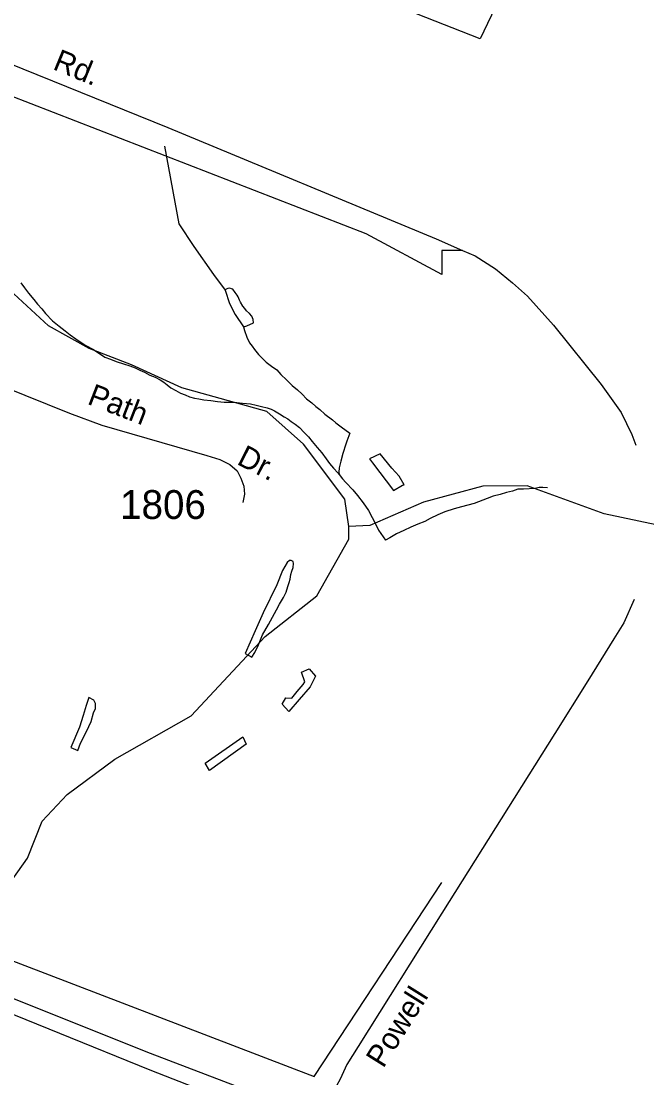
# Model space of a CAD drawing. Extents: x 2260773 to 2342389, y 552869 to 618546.
# Drawn here: x 2327254 to 2329965, y 580441 to 585022 of the extents above; entities that cross this region are included whole.
import ezdxf

# ---------------------------------------------------------------- set-up
doc = ezdxf.new("R2010")
doc.units = 0
for name, color, linetype in [('Exist Boundary Political Urban Extension UEB', 7, 'Continuous'), ('Exist Hydrographic Creek Single Shore', 7, 'Continuous'), ('Exist Hydrographic Misc Water Feature', 7, 'Continuous'), ('Exist Road Primary US Divided Attributed', 7, 'Continuous'), ('Exist Road Secondary Type 51 Attributed', 7, 'Continuous'), ('Exist Road Secondary Type 51 Label', 7, 'Continuous'), ('Exist Road Secondary Type 51 Number Label', 7, 'Continuous'), ('Map Preparation Inset Cut Line', 7, 'Continuous')]:
    doc.layers.add(name, color=color, linetype=linetype)

msp = doc.modelspace()

# ---------------------------------------------------------------- linework, layer by layer
at = {"layer": 'Exist Boundary Political Urban Extension UEB'}
for points in [[(2329076.9, 583924.2), (2328749.3, 584100.5), (2327102.5, 584738.6), (2325517.5, 585397.2), (2325007.6, 584916.5)], [(2326977.2, 580941.8), (2327020.2, 581023.5), (2328522.9, 580447.2), (2329076.9, 581287.8)]]:
    msp.add_lwpolyline(points, dxfattribs=at)
at = {"layer": 'Exist Hydrographic Creek Single Shore'}
for points in [[(2328673.6, 582831.9), (2328655.5, 582949.3), (2328477.5, 583188.3), (2328318.4, 583329.5), (2327950.6, 583432.7), (2327732.4, 583532.2), (2327548.5, 583603.6), (2327372.5, 583701.5), (2327145.5, 583908.9), (2327069.5, 584007.6), (2326976.6, 584197.4), (2326983.5, 584240.4), (2326941.5, 584281.3), (2326924.5, 584356.1), (2326839.4, 584503.6), (2326845.5, 584720.5), (2326926.5, 584914.1), (2327033.4, 585056.2)], [(2333084.7, 581589.2), (2332639.5, 581850.1), (2332079.5, 582096.6), (2331586.5, 582240.7), (2331068.6, 582341.3), (2330716.5, 582589.6), (2330473.5, 582720.9), (2330155.5, 582806.5), (2329780.4, 582886.4), (2329445.6, 583007.5), (2329254.5, 583006.3), (2328996.5, 582936.9), (2328764.4, 582835.5), (2328673.6, 582831.9)], [(2325729.4, 578486.2), (2325736.4, 578588.2), (2325784.4, 578819.8), (2326233.5, 579674.8), (2326430.5, 579961.7), (2326635.6, 580229.3), (2326724.6, 580505.2), (2326789.6, 580606.3), (2326950.1, 580730.3), (2327023.3, 580796.6), (2327047.3, 580853.8), (2327071.3, 580953.4), (2327121.6, 581112), (2327173.1, 581241.3), (2327281.5, 581394.1), (2327345.5, 581554.2), (2327452.5, 581670.1), (2327659.6, 581822.8), (2327990.5, 582010.1), (2328311.5, 582354.5), (2328534.5, 582530.9), (2328673.6, 582776.1), (2328673.6, 582831.9)]]:
    msp.add_lwpolyline(points, dxfattribs=at)
at = {"layer": 'Exist Hydrographic Misc Water Feature'}
for points in [[(2328710.9, 586666.3), (2328550.7, 586123), (2328936, 586007.1), (2329393.1, 585870.1), (2329553.5, 585829.9), (2329582, 585824.3), (2329613.7, 585816.3), (2329637.5, 585806.6), (2329645.9, 585800.9), (2329648, 585797), (2329647.8, 585788.9), (2329646.5, 585781), (2329642, 585774.7), (2329640.2, 585768.9), (2329632.6, 585758.7), (2329624.6, 585748.6), (2329599, 585692.4), (2329241.8, 584944.9), (2328374.4, 585287.4), (2327982.8, 585437.2), (2327655.3, 585561.5), (2327492.7, 585623.7)], [(2327874.9, 584480.6), (2327937, 584143.1), (2328002, 584045.8), (2328086.9, 583923.1), (2328137.8, 583855.5)], [(2327251.9, 583887.8), (2327267.9, 583866.3), (2327286, 583842.5), (2327308.5, 583814.8), (2327324.7, 583794.9), (2327342.8, 583775.1), (2327359, 583755.2), (2327389.5, 583723.5), (2327417.8, 583699.8), (2327443.9, 583680), (2327466.4, 583662.5), (2327490.2, 583644.7), (2327514.4, 583628.9), (2327534.7, 583615.3), (2327564.7, 583599.4), (2327592.7, 583581.8), (2327616.9, 583566), (2327641.3, 583556.2), (2327665.1, 583546.6), (2327697.1, 583536.9), (2327725.4, 583527.4), (2327747.4, 583519.6), (2327767.4, 583509.7), (2327788, 583500.1), (2327811.7, 583488), (2327834.1, 583478.6), (2327855.8, 583466.8), (2327872.2, 583457), (2327886.4, 583445.2), (2327902.2, 583433.1), (2327924.5, 583421.6), (2327944.6, 583409.6), (2327964.5, 583401.8), (2327982.8, 583394.1), (2328004.9, 583388.4), (2328022.9, 583384.5), (2328044.7, 583380.8), (2328075.2, 583377), (2328105.2, 583373.3), (2328133.1, 583369.9), (2328161.1, 583370.2), (2328188.8, 583368.4), (2328212.8, 583366.5), (2328247.1, 583362.9), (2328271.3, 583357.2), (2328294.8, 583351.6), (2328319, 583345.6), (2328337.1, 583340), (2328351.2, 583332.3), (2328373, 583320.4), (2328393.7, 583306.4), (2328409.5, 583298.7), (2328424, 583286.9), (2328441.7, 583275.3), (2328460.1, 583261.1), (2328480.2, 583239.4), (2328498.3, 583219.7), (2328514.5, 583199.8), (2328537, 583174.1), (2328556.9, 583150.4), (2328574.9, 583124.6), (2328589.7, 583105), (2328607.5, 583084.8), (2328626, 583063.4), (2328631.7, 583057.2)], [(2328217.1, 583696.7), (2328231.5, 583700.6), (2328261, 583714.8), (2328259.2, 583728.9), (2328252.8, 583742.8), (2328242.6, 583754.9), (2328230.5, 583766.5), (2328222.5, 583776.6), (2328214.7, 583786.3), (2328204, 583804.5), (2328200.3, 583812.4), (2328194.2, 583826.3), (2328189.9, 583834.2), (2328185.8, 583840.1), (2328181.7, 583846), (2328171.6, 583860.1), (2328165.7, 583861.8), (2328157.5, 583863.8), (2328149.3, 583863.5), (2328141.9, 583859.7), (2328137.8, 583855.5)], [(2328137.8, 583855.5), (2328156.2, 583797.9), (2328181, 583750), (2328217.1, 583696.7)], [(2328217.1, 583696.7), (2328221.2, 583680.7), (2328231.5, 583652.8), (2328243.8, 583627), (2328248.3, 583621), (2328254.2, 583612.8), (2328264.7, 583599.1), (2328282.7, 583577.4), (2328298.9, 583559.5), (2328314.9, 583543.7), (2328339.1, 583525.8), (2328361.3, 583510), (2328379.5, 583490.2), (2328403.7, 583466.7), (2328427.7, 583442.8), (2328450.5, 583423.2), (2328470.6, 583405.5), (2328490.5, 583385.5), (2328512.6, 583367.9), (2328530.9, 583352.3), (2328547.3, 583338), (2328569, 583318.5), (2328603.4, 583293.1), (2328617.6, 583281.2), (2328639.7, 583263.3), (2328678.1, 583235.6), (2328664.3, 583201.6), (2328660.2, 583187.6), (2328646.9, 583147.5), (2328639.3, 583115.3), (2328631.7, 583085.2), (2328630.1, 583067.2), (2328631.7, 583057.2)], [(2328906.7, 583010.2), (2328912.7, 583012.6), (2328892, 583050.1), (2328859.8, 583083.8), (2328808.7, 583147), (2328763.4, 583124.7), (2328775.7, 583107), (2328866.7, 582987.8), (2328906.7, 583010.2)], [(2328631.7, 583057.2), (2328646.5, 583037.6), (2328660.5, 583021.7), (2328690.8, 582990), (2328711.1, 582966.3), (2328735.1, 582934.7), (2328758.1, 582900.8), (2328774.3, 582870.8), (2328788.4, 582843.1), (2328802.3, 582815.4), (2328832.9, 582771.5)], [(2329534.2, 582998.9), (2329514.1, 583000.8), (2329498.3, 583000.6), (2329480.2, 582996.5), (2329430, 582993.9), (2329406.2, 582993.8), (2329382.4, 582985.3), (2329356.6, 582979), (2329328.5, 582970.7), (2329298.6, 582962.6), (2329272.7, 582952.3), (2329217, 582931.5), (2329189.3, 582923.5), (2329161, 582917.2), (2329129.4, 582908.6), (2329089.2, 582894.3), (2329059.7, 582882.2), (2329026.3, 582865.7), (2329002.1, 582853.5), (2328972.3, 582841), (2328942.4, 582828.9), (2328912.3, 582814.3), (2328880.7, 582800), (2328850.7, 582781.8), (2328832.9, 582771.5)], [(2328252.8, 582265.5), (2328266.8, 582285.7), (2328282.3, 582317.9), (2328299.8, 582362.3), (2328325, 582406.3), (2328342.8, 582438.5), (2328360.5, 582470.7), (2328372.6, 582494.9), (2328390, 582523.1), (2328401.7, 582547.3), (2328409.5, 582571.2), (2328415.4, 582589), (2328418.9, 582603.1), (2328422.8, 582623.1), (2328426.7, 582637.1), (2328432.4, 582653.3), (2328434.1, 582671.3), (2328432, 582679.3), (2328424.2, 582683.4), (2328416.2, 582683.4), (2328406.4, 582675.1), (2328386.5, 582640.8), (2328361.3, 582578.4), (2328303, 582457.9), (2328267.6, 582379.7), (2328224.3, 582281.2), (2328252.8, 582265.5)], [(2328413.2, 582029.3), (2328384.9, 582061.2), (2328400.6, 582089.2), (2328426.3, 582087.8), (2328450.1, 582115.8), (2328475.9, 582146), (2328483.5, 582158.2), (2328469.1, 582200.1), (2328501.3, 582214.3), (2328529.2, 582182.5), (2328506.3, 582136.6), (2328458.5, 582082.1), (2328413.2, 582029.3)], [(2327499.2, 581859.8), (2327511.3, 581891.7), (2327536.8, 581942.2), (2327556.5, 581986.3), (2327567.9, 582024.3), (2327575.5, 582042.6), (2327575.5, 582050.3), (2327575.3, 582064.5), (2327569.2, 582078.4), (2327546.8, 582089.9), (2327535.7, 582055.9), (2327522, 582011.7), (2327506.4, 581961.8), (2327469.7, 581873.2), (2327499.2, 581859.8)], [(2328070.3, 581773.9), (2328051.7, 581805.5), (2328214.3, 581919.3), (2328229, 581887.5), (2328070.3, 581773.9)]]:
    msp.add_lwpolyline(points, dxfattribs=at)
at = {"layer": 'Exist Road Primary US Divided Attributed'}
for points in [[(2328551.1, 580261.6), (2328291, 580364.6), (2327814.3, 580546.4), (2326963.8, 580887.3)], [(2326942.5, 580828.8), (2327027.6, 580794.8), (2327811.9, 580476.1), (2328262.1, 580299.5), (2328522.3, 580193.5)]]:
    msp.add_lwpolyline(points, dxfattribs=at)
at = {"layer": 'Exist Road Secondary Type 51 Attributed'}
for points in [[(2325403.9, 585580.5), (2327070.9, 584891.5), (2327889.1, 584561.4), (2329051.2, 584078.7), (2329166.4, 584028.3), (2329221.1, 584004.4), (2329309, 583947.7), (2329383.2, 583887.2), (2329447.6, 583830.5), (2329559.9, 583704.4), (2329766.9, 583446.5), (2329852.9, 583325.3), (2329899.8, 583229.5), (2329917.3, 583184.6)], [(2326507.6, 583642.2), (2326898.8, 583527.6), (2327172.4, 583440.2), (2327463.8, 583323.3), (2327602.8, 583270), (2328057.6, 583139.1), (2328114.6, 583122), (2328158.2, 583100.6), (2328189.3, 583072.5), (2328205.5, 583041.4), (2328218.9, 583005.9), (2328221.8, 582971.8), (2328214.4, 582934.8)], [(2329909.9, 582515), (2329865.5, 582414.3), (2329821.1, 582344.8), (2329708.7, 582162.7), (2329565.3, 581934.8), (2329076.9, 581155.7), (2328714.1, 580576.9), (2328665.2, 580499.9), (2328635.7, 580436.3), (2328603.7, 580378.1), (2328570.9, 580304.2), (2328551.1, 580261.6)]]:
    msp.add_lwpolyline(points, dxfattribs=at)
at = {"layer": 'Map Preparation Inset Cut Line'}
msp.add_lwpolyline([(2329166.4, 584028.3), (2329076.9, 584028.3), (2329076.9, 583924.2)], dxfattribs=at)

# ---------------------------------------------------------------- texts
at = {"layer": 'Exist Road Secondary Type 51 Label'}
for s, rotation, p in [('Rd.', 337.6842, (2327386.7, 584815.1)), ('Path', 338.7945, (2327536.1, 583364)), ('Dr.', 332.9917, (2328183.9, 583103.4)), ('Powell', 57.9416, (2328822.7, 580479.9))]:
    msp.add_text(s, height=95, rotation=rotation, dxfattribs=at).set_placement(p)
at = {"layer": 'Exist Road Secondary Type 51 Number Label'}
msp.add_text('1806', height=125, dxfattribs=at).set_placement((2327682.4, 582864.1))

doc.saveas('drawing.dxf')
